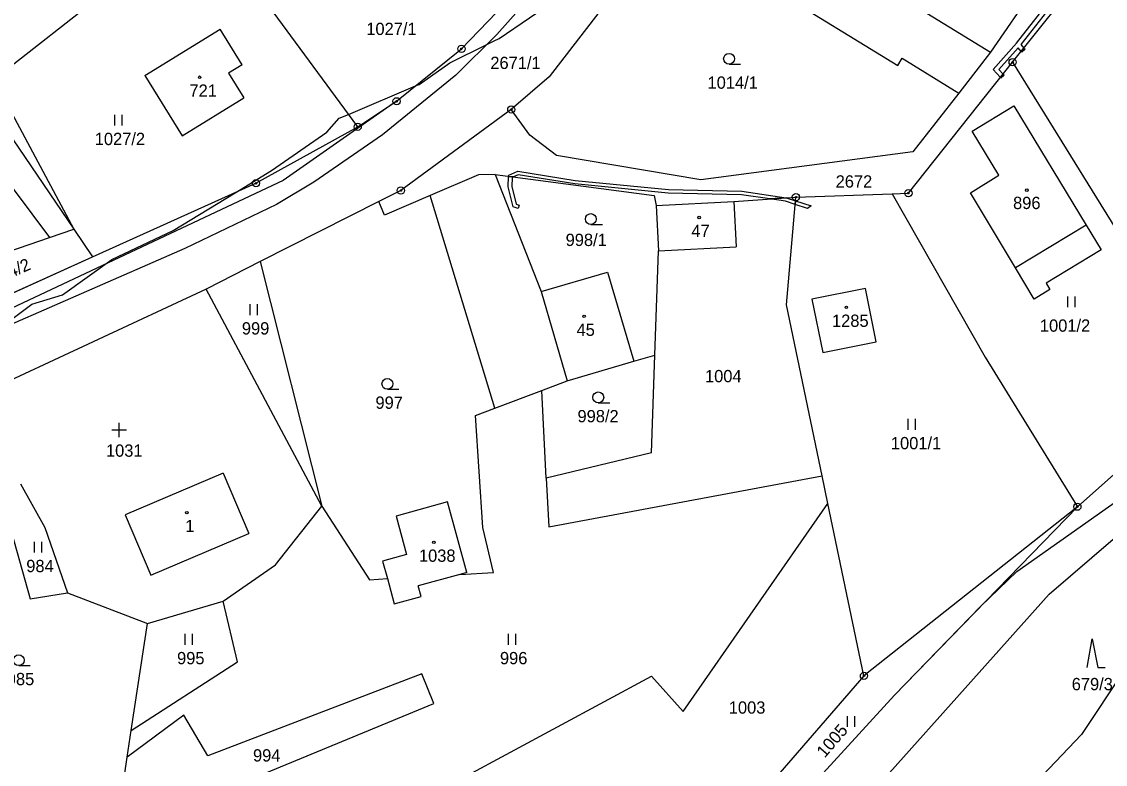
# Model space of a CAD drawing. Extents: x -439246 to -433691, y -1130252 to -1121148.
# Drawn here: x -437973 to -437823.2, y -1124223.5 to -1124120.8 of the extents above; entities that cross this region are included whole.
import ezdxf

# ---------------------------------------------------------------- set-up
doc = ezdxf.new("R2010")
doc.units = 0
for name, color, linetype in [('Vrstva 1', 7, 'Continuous'), ('Vrstva 16', 7, 'Continuous'), ('Vrstva 18', 7, 'Continuous'), ('Vrstva 19', 7, 'Continuous'), ('Vrstva 24', 7, 'Continuous'), ('Vrstva 25', 7, 'Continuous'), ('Vrstva 3', 7, 'Continuous'), ('Vrstva 30', 7, 'Continuous'), ('Vrstva 37', 7, 'Continuous'), ('Vrstva 4', 7, 'Continuous'), ('Vrstva 52', 7, 'Continuous')]:
    doc.layers.add(name, color=color, linetype=linetype)

msp = doc.modelspace()

# ---------------------------------------------------------------- linework, layer by layer
at = {"layer": 'Vrstva 1'}
for p, q in [((-437841.62, -1124135.96), (-437835.86, -1124132.46)), ((-437835.86, -1124132.46), (-437825.85, -1124148.97)), ((-437837.92, -1124142.04), (-437841.62, -1124135.96)), ((-437841.82, -1124144.48), (-437837.92, -1124142.04)), ((-437835.6, -1124154.87), (-437841.82, -1124144.48)), ((-437825.85, -1124148.97), (-437823.78, -1124152.38)), ((-437823.78, -1124152.38), (-437831.39, -1124157)), ((-437833.02, -1124159.18), (-437835.6, -1124154.87)), ((-437830.87, -1124157.85), (-437833.02, -1124159.18)), ((-437831.39, -1124157), (-437830.87, -1124157.85))]:
    msp.add_line(p, q, dxfattribs=at)
for points in [[(-437926.56, -1124135.35), (-437948.03, -1124106.15)], [(-437883.22, -1124106.54), (-437900.07, -1124128.46)], [(-437900.08, -1124111.93), (-437912.21, -1124124.57)], [(-437836.01, -1124126.42), (-437825.76, -1124113.54)], [(-437976.91, -1124128.81), (-437961.34, -1124116.59)], [(-437902.03, -1124116.58), (-437907.32, -1124122.59)], [(-437869.33, -1124116.12), (-437851.87, -1124126.86)], [(-437833.04, -1124116.25), (-437839.05, -1124125.04)], [(-437993.37, -1124118.3), (-437969.15, -1124150.67)], [(-437955.97, -1124128.24), (-437945.59, -1124121.84)], [(-437942.54, -1124126.77), (-437945.59, -1124121.84)], [(-437907.32, -1124122.59), (-437913.01, -1124128.23)], [(-437921.18, -1124131.83), (-437912.21, -1124124.57)], [(-437851.87, -1124126.86), (-437851.27, -1124125.88)], [(-437851.27, -1124125.88), (-437843.45, -1124130.69)], [(-437850.42, -1124144.53), (-437836.01, -1124126.42)], [(-437839.05, -1124125.04), (-437843.45, -1124130.69)], [(-437836.01, -1124126.42), (-437810.76, -1124167.22)], [(-437942.54, -1124126.77), (-437944.41, -1124127.93)], [(-437976.91, -1124128.81), (-437965.81, -1124149.52)], [(-437955.97, -1124128.24), (-437950.82, -1124136.58)], [(-437944.41, -1124127.93), (-437942.31, -1124131.33)], [(-437913.01, -1124128.23), (-437923.12, -1124136.46)], [(-437900.07, -1124128.46), (-437905.32, -1124132.95)], [(-437978.54, -1124130.83), (-437965.81, -1124149.52)], [(-437843.45, -1124130.69), (-437849.79, -1124138.82)], [(-437950.82, -1124136.58), (-437942.31, -1124131.33)], [(-437926.56, -1124135.35), (-437921.18, -1124131.83)], [(-437905.32, -1124132.95), (-437920.59, -1124144.17)], [(-437902.78, -1124136.52), (-437905.32, -1124132.95)], [(-437940.62, -1124143.17), (-437926.56, -1124135.35)], [(-437923.12, -1124136.46), (-437932.61, -1124143.01)], [(-437899.09, -1124139.32), (-437902.78, -1124136.52)], [(-437879.11, -1124142.68), (-437899.09, -1124139.32)], [(-437849.79, -1124138.82), (-437879.11, -1124142.68)], [(-437909.87, -1124142), (-437916.54, -1124144.86)], [(-437907.56, -1124141.96), (-437909.87, -1124142)], [(-437907.56, -1124141.96), (-437885.55, -1124144.87)], [(-437907.56, -1124141.96), (-437901.21, -1124158.14)], [(-437963.2, -1124153.35), (-437940.62, -1124143.17)], [(-437932.61, -1124143.01), (-437937.77, -1124146.1)], [(-437920.59, -1124144.17), (-437923.63, -1124145.7)], [(-437923.63, -1124145.7), (-437940.04, -1124153.97)], [(-437922.83, -1124147.56), (-437923.63, -1124145.7)], [(-437916.54, -1124144.86), (-437922.83, -1124147.56)], [(-437907.59, -1124174.26), (-437916.54, -1124144.86)], [(-437885.55, -1124144.87), (-437885.28, -1124146.23)], [(-437885.28, -1124146.23), (-437874.57, -1124145.67)], [(-437874.57, -1124145.67), (-437865.97, -1124145.07)], [(-437874.57, -1124145.67), (-437874.24, -1124151.93)], [(-437867.28, -1124159.99), (-437865.97, -1124145.07)], [(-437865.97, -1124145.07), (-437852.66, -1124144.61)], [(-437852.66, -1124144.61), (-437850.42, -1124144.53)], [(-437852.66, -1124144.61), (-437839.83, -1124167.21)], [(-437937.77, -1124146.1), (-437950.44, -1124152.19)], [(-437885.28, -1124146.23), (-437884.95, -1124152.49)], [(-437969.15, -1124150.67), (-437965.81, -1124149.52)], [(-437965.81, -1124149.52), (-437963.2, -1124153.35)], [(-437998.79, -1124160.85), (-437969.15, -1124150.67)], [(-437950.44, -1124152.19), (-438007.84, -1124177.25)], [(-437991.38, -1124166.06), (-437963.2, -1124153.35)], [(-437885.46, -1124166.92), (-437884.95, -1124152.49)], [(-437884.95, -1124152.49), (-437874.24, -1124151.93)], [(-437940.04, -1124153.97), (-437947.52, -1124157.82)], [(-437940.04, -1124153.97), (-437931.51, -1124187.82)], [(-437901.21, -1124158.14), (-437892, -1124155.45)], [(-437892, -1124155.45), (-437888.4, -1124167.78)], [(-437947.52, -1124157.82), (-437978.78, -1124172.37)], [(-437931.51, -1124187.82), (-437947.52, -1124157.82)], [(-437856.37, -1124157.72), (-437863.76, -1124159.2)], [(-437854.89, -1124165.08), (-437856.37, -1124157.72)], [(-437863.76, -1124159.2), (-437862.24, -1124166.57)], [(-437862.35, -1124183.6), (-437867.28, -1124159.99)], [(-437862.24, -1124166.57), (-437854.89, -1124165.08)], [(-437897.61, -1124170.47), (-437888.4, -1124167.78)], [(-437888.4, -1124167.78), (-437885.46, -1124166.92)], [(-437885.94, -1124180.45), (-437885.46, -1124166.92)], [(-437839.83, -1124167.21), (-437827.06, -1124187.89)], [(-437901.11, -1124171.8), (-437897.61, -1124170.47)], [(-437827.06, -1124187.89), (-437808.27, -1124171.24)], [(-437907.59, -1124174.26), (-437901.11, -1124171.8)], [(-437900.49, -1124183.93), (-437901.11, -1124171.8)], [(-437910.28, -1124175.29), (-437907.59, -1124174.26)], [(-437909.24, -1124190.75), (-437910.28, -1124175.29)], [(-437885.94, -1124180.45), (-437900.49, -1124183.93)], [(-437945.17, -1124183.25), (-437958.71, -1124189.03)], [(-437945.17, -1124183.25), (-437941.61, -1124191.6)], [(-437973.19, -1124184.75), (-437969.83, -1124190.76)], [(-437900.49, -1124183.93), (-437900.15, -1124190.67)], [(-437900.15, -1124190.67), (-437862.35, -1124183.6)], [(-437861.55, -1124187.44), (-437862.35, -1124183.6)], [(-437975.96, -1124186), (-437971.86, -1124200.64)], [(-437937.9, -1124195.95), (-437931.51, -1124187.82)], [(-437931.51, -1124187.82), (-437924.94, -1124197.99)], [(-437914.14, -1124187.22), (-437921.26, -1124189.18)], [(-437911.45, -1124196.98), (-437914.14, -1124187.22)], [(-437881.56, -1124216.22), (-437861.55, -1124187.44)], [(-437856.56, -1124211.29), (-437861.55, -1124187.44)], [(-437958.71, -1124189.03), (-437955.15, -1124197.38)], [(-437921.26, -1124189.18), (-437919.8, -1124194.48)], [(-437827.06, -1124187.89), (-437856.56, -1124211.29)], [(-437852.34, -1124213.96), (-437827.06, -1124187.89)], [(-437969.83, -1124190.76), (-437966.66, -1124199.81)], [(-437907.78, -1124196.98), (-437909.24, -1124190.75)], [(-437955.15, -1124197.38), (-437941.61, -1124191.6)], [(-437830.95, -1124199.98), (-437822.11, -1124192.37)], [(-437919.8, -1124194.48), (-437923.13, -1124195.4)], [(-437945.16, -1124200.97), (-437937.9, -1124195.95)], [(-437923.13, -1124195.4), (-437922.46, -1124197.84)], [(-437924.94, -1124197.99), (-437922.46, -1124197.84)], [(-437922.46, -1124197.84), (-437921.5, -1124201.33)], [(-437912.43, -1124197.25), (-437918.18, -1124198.84)], [(-437911.45, -1124196.98), (-437912.43, -1124197.25)], [(-437912.43, -1124197.25), (-437907.78, -1124196.98)], [(-437971.86, -1124200.64), (-437966.66, -1124199.81)], [(-437966.66, -1124199.81), (-437955.64, -1124204.02)], [(-437917.78, -1124200.3), (-437918.18, -1124198.84)], [(-437955.64, -1124204.02), (-437945.16, -1124200.97)], [(-437943.17, -1124209.34), (-437945.16, -1124200.97)], [(-437921.5, -1124201.33), (-437917.78, -1124200.3)], [(-437864.67, -1124237.67), (-437830.95, -1124199.98)], [(-437957.86, -1124218.84), (-437955.64, -1124204.02)], [(-437957.86, -1124218.84), (-437943.17, -1124209.34)], [(-437917.69, -1124211.01), (-437947.29, -1124222.34)], [(-437916.03, -1124215.11), (-437917.69, -1124211.01)], [(-437911.95, -1124225.34), (-437885.93, -1124211.33)], [(-437885.93, -1124211.33), (-437881.56, -1124216.22)], [(-437856.56, -1124211.29), (-437873.55, -1124230.87)], [(-437870.61, -1124233.92), (-437852.34, -1124213.96)], [(-437960.31, -1124233.42), (-437916.03, -1124215.11)], [(-437950.61, -1124216.72), (-437958.42, -1124222.54)], [(-437947.29, -1124222.34), (-437950.61, -1124216.72)], [(-437958.42, -1124222.54), (-437957.86, -1124218.84)], [(-437958.79, -1124225.04), (-437958.42, -1124222.54)]]:
    msp.add_lwpolyline(points, dxfattribs=at)
at = {"layer": 'Vrstva 24'}
for centre, radius in [((-437912.21, -1124124.57), 0.5), ((-437912.21, -1124124.57), 0.1), ((-437836.01, -1124126.42), 0.5), ((-437836.01, -1124126.42), 0.1), ((-437921.18, -1124131.83), 0.5), ((-437921.18, -1124131.83), 0.1), ((-437905.32, -1124132.95), 0.5), ((-437905.32, -1124132.95), 0.1), ((-437926.56, -1124135.35), 0.5), ((-437926.56, -1124135.35), 0.1), ((-437940.62, -1124143.17), 0.5), ((-437940.62, -1124143.17), 0.1), ((-437920.59, -1124144.17), 0.5), ((-437920.59, -1124144.17), 0.1), ((-437850.42, -1124144.53), 0.5), ((-437865.97, -1124145.07), 0.5), ((-437865.97, -1124145.07), 0.1), ((-437850.42, -1124144.53), 0.1), ((-437827.06, -1124187.89), 0.5), ((-437827.06, -1124187.89), 0.1), ((-437856.56, -1124211.29), 0.5), ((-437856.56, -1124211.29), 0.1)]:
    msp.add_circle(centre, radius, dxfattribs=at)
at = {"layer": 'Vrstva 25'}
for p, q in [((-437875.22, -1124126.7), (-437873.62, -1124126.7)), ((-437960.12, -1124135.18), (-437960.12, -1124133.68)), ((-437959.12, -1124135.18), (-437959.12, -1124133.68)), ((-437894.33, -1124148.86), (-437892.73, -1124148.86)), ((-437828.37, -1124160.3), (-437828.37, -1124158.8)), ((-437827.37, -1124160.3), (-437827.37, -1124158.8)), ((-437941.41, -1124161.38), (-437941.41, -1124159.88)), ((-437940.41, -1124161.38), (-437940.41, -1124159.88)), ((-437922.45, -1124171.65), (-437920.85, -1124171.65)), ((-437893.3, -1124173.52), (-437891.7, -1124173.52)), ((-437850.44, -1124177.25), (-437850.44, -1124175.75)), ((-437849.44, -1124177.25), (-437849.44, -1124175.75)), ((-437960.54, -1124177.28), (-437958.54, -1124177.28)), ((-437959.54, -1124178.28), (-437959.54, -1124176.28)), ((-437971.23, -1124194.24), (-437971.23, -1124192.74)), ((-437970.23, -1124194.24), (-437970.23, -1124192.74)), ((-437950.39, -1124206.98), (-437950.39, -1124205.48)), ((-437949.39, -1124206.98), (-437949.39, -1124205.48)), ((-437905.7, -1124206.98), (-437905.7, -1124205.48)), ((-437904.7, -1124206.98), (-437904.7, -1124205.48)), ((-437973.43, -1124209.87), (-437971.83, -1124209.87)), ((-437858.83, -1124218.34), (-437858.83, -1124216.84)), ((-437857.83, -1124218.34), (-437857.83, -1124216.84))]:
    msp.add_line(p, q, dxfattribs=at)
msp.add_lwpolyline([(-437825.72, -1124210.14), (-437825.02, -1124206.14), (-437824.22, -1124210.14), (-437823.22, -1124210.14)], dxfattribs=at)
for centre, radius in [((-437875.22, -1124125.95), 0.75), ((-437948.41, -1124128.5), 0.175), ((-437834.04, -1124144.12), 0.175), ((-437894.33, -1124148.11), 0.75), ((-437879.36, -1124147.89), 0.175), ((-437859, -1124160.32), 0.175), ((-437895.26, -1124161.57), 0.175), ((-437922.45, -1124170.9), 0.75), ((-437893.3, -1124172.77), 0.75), ((-437950.18, -1124188.71), 0.175), ((-437916.03, -1124192.81), 0.175), ((-437973.43, -1124209.12), 0.75)]:
    msp.add_circle(centre, radius, dxfattribs=at)
at = {"layer": 'Vrstva 3'}
for points in [[(-437955.97, -1124128.24), (-437945.59, -1124121.84)], [(-437942.54, -1124126.77), (-437945.59, -1124121.84)], [(-437942.54, -1124126.77), (-437944.41, -1124127.93)], [(-437955.97, -1124128.24), (-437950.82, -1124136.58)], [(-437944.41, -1124127.93), (-437942.31, -1124131.33)], [(-437950.82, -1124136.58), (-437942.31, -1124131.33)], [(-437841.62, -1124135.96), (-437835.86, -1124132.46)], [(-437835.86, -1124132.46), (-437825.85, -1124148.97)], [(-437837.92, -1124142.04), (-437841.62, -1124135.96)], [(-437841.82, -1124144.48), (-437837.92, -1124142.04)], [(-437885.28, -1124146.23), (-437874.57, -1124145.67)], [(-437874.57, -1124145.67), (-437874.24, -1124151.93)], [(-437835.6, -1124154.87), (-437841.82, -1124144.48)], [(-437885.28, -1124146.23), (-437884.95, -1124152.49)], [(-437825.85, -1124148.97), (-437835.6, -1124154.87)], [(-437884.95, -1124152.49), (-437874.24, -1124151.93)], [(-437901.21, -1124158.14), (-437892, -1124155.45)], [(-437892, -1124155.45), (-437888.4, -1124167.78)], [(-437856.37, -1124157.72), (-437863.76, -1124159.2)], [(-437854.89, -1124165.08), (-437856.37, -1124157.72)], [(-437901.21, -1124158.14), (-437897.61, -1124170.47)], [(-437863.76, -1124159.2), (-437862.24, -1124166.57)], [(-437862.24, -1124166.57), (-437854.89, -1124165.08)], [(-437897.61, -1124170.47), (-437888.4, -1124167.78)], [(-437945.17, -1124183.25), (-437958.71, -1124189.03)], [(-437945.17, -1124183.25), (-437941.61, -1124191.6)], [(-437914.14, -1124187.22), (-437921.26, -1124189.18)], [(-437911.45, -1124196.98), (-437914.14, -1124187.22)], [(-437958.71, -1124189.03), (-437955.15, -1124197.38)], [(-437921.26, -1124189.18), (-437919.8, -1124194.48)], [(-437955.15, -1124197.38), (-437941.61, -1124191.6)], [(-437919.8, -1124194.48), (-437923.13, -1124195.4)], [(-437923.13, -1124195.4), (-437922.46, -1124197.84)], [(-437922.46, -1124197.84), (-437921.5, -1124201.33)], [(-437912.43, -1124197.25), (-437918.18, -1124198.84)], [(-437911.45, -1124196.98), (-437912.43, -1124197.25)], [(-437917.78, -1124200.3), (-437918.18, -1124198.84)], [(-437921.5, -1124201.33), (-437917.78, -1124200.3)]]:
    msp.add_lwpolyline(points, dxfattribs=at)
at = {"layer": 'Vrstva 30'}
for points in [[(-437821.75, -1124110.17), (-437824.7, -1124111.9), (-437829.81, -1124117.47), (-437834.87, -1124123.99), (-437834.45, -1124124.46), (-437834.83, -1124124.94), (-437835.26, -1124124.45), (-437837.92, -1124127.42), (-437837.32, -1124128.07), (-437837.7, -1124128.54), (-437838.72, -1124127.42), (-437835.49, -1124123.81), (-437830.27, -1124117.09), (-437825.08, -1124111.42), (-437822.01, -1124109.63)], [(-437834.29, -1124124.64), (-437834.75, -1124125.04), (-437834.83, -1124124.94), (-437834.45, -1124124.46), (-437834.29, -1124124.64)], [(-437837.19, -1124128.21), (-437837.63, -1124128.61), (-437837.7, -1124128.54), (-437837.32, -1124128.07), (-437837.19, -1124128.21)], [(-437921.18, -1124131.83), (-437936.86, -1124142.8), (-437982.27, -1124164.11), (-437984.71, -1124163.05), (-437963.2, -1124153.35), (-437940.62, -1124143.17), (-437926.56, -1124135.35), (-437921.18, -1124131.83)], [(-437904.23, -1124146.17), (-437904.39, -1124146.65), (-437905.08, -1124146.42), (-437905.76, -1124143.66), (-437905.69, -1124142.21), (-437905.04, -1124142.29), (-437905.2, -1124142.36), (-437905.26, -1124143.62), (-437904.67, -1124146.03), (-437904.23, -1124146.17)], [(-437896.53, -1124143.26), (-437904.37, -1124142.01), (-437905.04, -1124142.29), (-437905.69, -1124142.21), (-437905.68, -1124142.05), (-437904.44, -1124141.49), (-437896.47, -1124142.76), (-437883.59, -1124144.03), (-437873.44, -1124144.24), (-437867.3, -1124145.16), (-437869.6, -1124145.32), (-437873.48, -1124144.74), (-437883.63, -1124144.53), (-437896.53, -1124143.26)], [(-437867.3, -1124145.16), (-437866.02, -1124145.59), (-437866.06, -1124146.1), (-437867.42, -1124145.65), (-437869.6, -1124145.32), (-437867.3, -1124145.16)], [(-437866.02, -1124145.59), (-437863.87, -1124146.3), (-437864.39, -1124146.65), (-437866.06, -1124146.1), (-437866.02, -1124145.59)]]:
    msp.add_lwpolyline(points, dxfattribs=at)
at = {"layer": 'Vrstva 37'}
for centre in [(-437948.41, -1124128.5), (-437834.04, -1124144.12), (-437879.36, -1124147.89), (-437859, -1124160.32), (-437895.26, -1124161.57), (-437950.18, -1124188.71), (-437916.03, -1124192.81)]:
    msp.add_circle(centre, 0.175, dxfattribs=at)
at = {"layer": 'Vrstva 4'}
msp.add_line((-437825.85, -1124148.97), (-437835.6, -1124154.87), dxfattribs=at)
for points in [[(-437865, -1124109.07), (-437839.05, -1124125.04)], [(-437901.21, -1124158.14), (-437897.61, -1124170.47)]]:
    msp.add_lwpolyline(points, dxfattribs=at)
at = {"layer": 'Vrstva 52'}
for points in [[(-437975.86, -1124163.07), (-437971.61, -1124159.88), (-437967.36, -1124158.61), (-437960.56, -1124153.72), (-437952.06, -1124149.68), (-437943.5, -1124144.47), (-437938.46, -1124141.4), (-437930.82, -1124136.09), (-437929.11, -1124134.17), (-437927.83, -1124133.63), (-437918.56, -1124129.71), (-437918.07, -1124129.5), (-437913.82, -1124126.53), (-437908.72, -1124123.97), (-437907.71, -1124123.47), (-437907.02, -1124123.13), (-437898.6, -1124117.4)], [(-437955.67, -1124329.01), (-437952.55, -1124324.65), (-437949.55, -1124320.45), (-437941.23, -1124308.82), (-437914.88, -1124283.75), (-437912.18, -1124281.59), (-437907.62, -1124277.95), (-437907.44, -1124277.8), (-437899.55, -1124266.45), (-437892.53, -1124256.36), (-437889.21, -1124251.61), (-437887.05, -1124248.48), (-437884.71, -1124245.72), (-437873.45, -1124235.95), (-437873.01, -1124235.48), (-437870.61, -1124233.92), (-437852.34, -1124213.96), (-437840.45, -1124201.7), (-437835.42, -1124196.85), (-437816.83, -1124183.73)], [(-437808.86, -1124192.82), (-437826.49, -1124219.37), (-437838.18, -1124231.7)]]:
    msp.add_lwpolyline(points, dxfattribs=at)

# ---------------------------------------------------------------- texts
at = {"layer": 'Vrstva 16'}
msp.add_text('2671/1', height=1.7, dxfattribs=at).set_placement((-437908.22, -1124127.36))
at = {"layer": 'Vrstva 18'}
for s, p in [('1027/1', (-437925.37, -1124122.66)), ('1014/1', (-437878.19, -1124130.09)), ('1027/2', (-437962.91, -1124137.88)), ('2672', (-437860.48, -1124143.76)), ('998/1', (-437897.81, -1124151.84)), ('999', (-437942.57, -1124164.08)), ('1001/2', (-437832.24, -1124163.69)), ('1004', (-437878.54, -1124170.68)), ('997', (-437924.1, -1124174.35)), ('998/2', (-437896.17, -1124176.22)), ('1001/1', (-437852.84, -1124179.95)), ('1031', (-437961.36, -1124180.98)), ('984', (-437972.38, -1124196.94)), ('995', (-437951.53, -1124209.68)), ('996', (-437906.89, -1124209.68)), ('985', (-437975.07, -1124212.57)), ('679/3', (-437827.84, -1124213.27)), ('1003', (-437875.25, -1124216.51)), ('994', (-437941.03, -1124223.13))]:
    msp.add_text(s, height=1.7, dxfattribs=at).set_placement(p)
for s, rotation, p in [('1014/2', 23.5613, (-437977.99, -1124157.8)), ('1005', 49.1074, (-437861.99, -1124222.71))]:
    msp.add_text(s, height=1.7, rotation=rotation, dxfattribs=at).set_placement(p)
at = {"layer": 'Vrstva 19'}
for s, p in [('721', (-437949.82, -1124131.2)), ('896', (-437835.95, -1124146.73)), ('47', (-437880.42, -1124150.59)), ('1285', (-437860.98, -1124163.02)), ('45', (-437896.3, -1124164.27)), ('1', (-437950.4, -1124191.41)), ('1038', (-437918.09, -1124195.51))]:
    msp.add_text(s, height=1.7, dxfattribs=at).set_placement(p)

doc.saveas('drawing.dxf')
